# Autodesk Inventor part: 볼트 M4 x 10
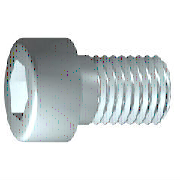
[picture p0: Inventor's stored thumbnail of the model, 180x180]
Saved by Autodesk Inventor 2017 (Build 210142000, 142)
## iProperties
IsCustomPart: 0
Created: 2012-02
Part Number: 볼트 M4 x 10
Material: 강철, 연강
Description: 6각 소켓 머리 캡 나사
Document SubType Name: Modeling
Standard: ISO 4762
Designer: mduedu
Standard Revision: Fourth edition 2004-03-01
Standards Organization: ISO
Language: ko-KR
Size Designation: M4 x 12
Categories: <MemberInstance><Categories><Category DisplayName="조임쇠" InternalName="e4da775c-781d-43d5-af7c-5136215cf5a6" Mnemonic="FSTN"><Category DisplayName="볼트" InternalN
Density: 7.75 g/cm^3
Appearance: 강철
Author: mduedu
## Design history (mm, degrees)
sketch "스케치1"
  geometry: L1 (-1, 0)-(10, 0); L2 (10, 0)-(10, 2); L3 (10, 2)-(1.75, 2); L4 (1.75, 2)-(1.32, 2); L5 (1.32, 2)-(0, 2); L6 (0, 2)-(0, 3.5); L7 (0, 3.5)-(-4, 3.5); L8 (-4, 3.5)-(-4, 1.732); L9 (-4, 1.732)-(-2, 1.732); L10 (-2, 1.732)-(-1, 0); L11 (-7.2, 0)-(15.2, 0) reference; L12 (0, -0.7)-(0, 4.2) reference; L13 (1.75, 2)-(0, 2)
  constraints: 22 end point, 6 parallel, 2 collinear, 2 perpendicular, 1 horizontal, 1 point on line
  dimensions: "d1" = 8.25 distance from line of L3.end L2 (= GEL); "d2" = 0.42952 distance of L4.end L3.end (computed from GAL); "d3" = 4 distance between parallel lines of L8 L6 (= KOH); "d4" = 2 distance of L8.end L9.end (= INTI); "d5" = 60 deg angle of L10 L1; "d6" = 4 diameter of L3 L1 (= GD); "d7" = 4 diameter of L5 L1 (= BDM); "d8" = 3.4641 diameter of L9 L1 (= 1.1547 x SW); "d9" = 7 diameter of L7 L1 (= KOD); "d26" = 10 distance between parallel lines of L12 L2 (= NLG)
revolve "본체" sketch "스케치1" stored, may be unused: angle "d10" = 90 deg
sketch "스케치2"
  geometry: L1 (0, -4.9)-(0, 4.9) reference; L2 (-4.9, 0)-(4.9, 0) reference; L3 (1.732, 0)-(0.866, -1.5); L4 (0.866, -1.5)-(-0.866, -1.5); L5 (-0.866, -1.5)-(-1.732, 0); L6 (-1.732, 0)-(-0.866, 1.5); L7 (-0.866, 1.5)-(0.866, 1.5); L8 (0.866, 1.5)-(1.732, 0); 2 further points
  constraints: 12 end point, 1 coincident, 1 horizontal alignment, 1 point on line, 12 other
extrude "슬롯" join sketch "스케치2" stored distance "d11" = 10; taper "d12" = 0 deg
workplane "Work Plane1"
fillet "Fillet2" dims "d30" = 0.1 (= R)
body "Solid1"
fillet "모깎기1" dims "d17" = 0.4 (= RR)
feature "스레드" dims "d13" = 8.25 (= GEL), "d14" = 0
chamfer "모따기1" distance "d15" = 0.42941 (= -0.5 x SPD + 0.5 x GD); stored, may be unused: second distance "d16" = 0.42941 (= GUL), angle "d27" = 45 deg
other parameters: "GD" = 4 [user parameter; used in 2 equation terms], "NLG" = 10 [user parameter; used in 1 equation term], "GEL" = 8.25 [user parameter; used in 2 equation terms], "KOD" = 7 [user parameter; used in 1 equation term], "KOH" = 4 [user parameter; used in 1 equation term], "INTI" = 2 [user parameter; used in 1 equation term], "GAL" = 0.42941 (= 0.61345 x PTC) [user parameter; used in 1 equation term], "GUL" = 0.42941 (= 0.61345 x PTC) [user parameter; used in 1 equation term], "BDM" = 4 (= NND) [user parameter; used in 1 equation term], "SW" = 3 [user parameter; used in 2 equation terms], "RR" = 0.4 [user parameter; used in 1 equation term], "SPD" = 3.14117 (= NND - 1.2269 x PTC) [user parameter; used in 1 equation term], "d19" = 0, "d28" = 0, "d29" = 0, "R" = 0.1 [user parameter; used in 1 equation term], "TOA" = 30 deg [user parameter], "GD1" = 3.14117 (= THREADDIA - 1.2269 x PTC) [user parameter], "THREADDIA" = 4 [user parameter; used in 1 equation term], "FAWI" = 45 deg [user parameter], "TPU" = 14.28571 (computed from PTC) [user parameter], "PTC" = 0.7 [user parameter; used in 5 equation terms], "NND" = 4 [user parameter; used in 2 equation terms], "E0" = 3.465 (= 1.155 x SW) [user parameter]
